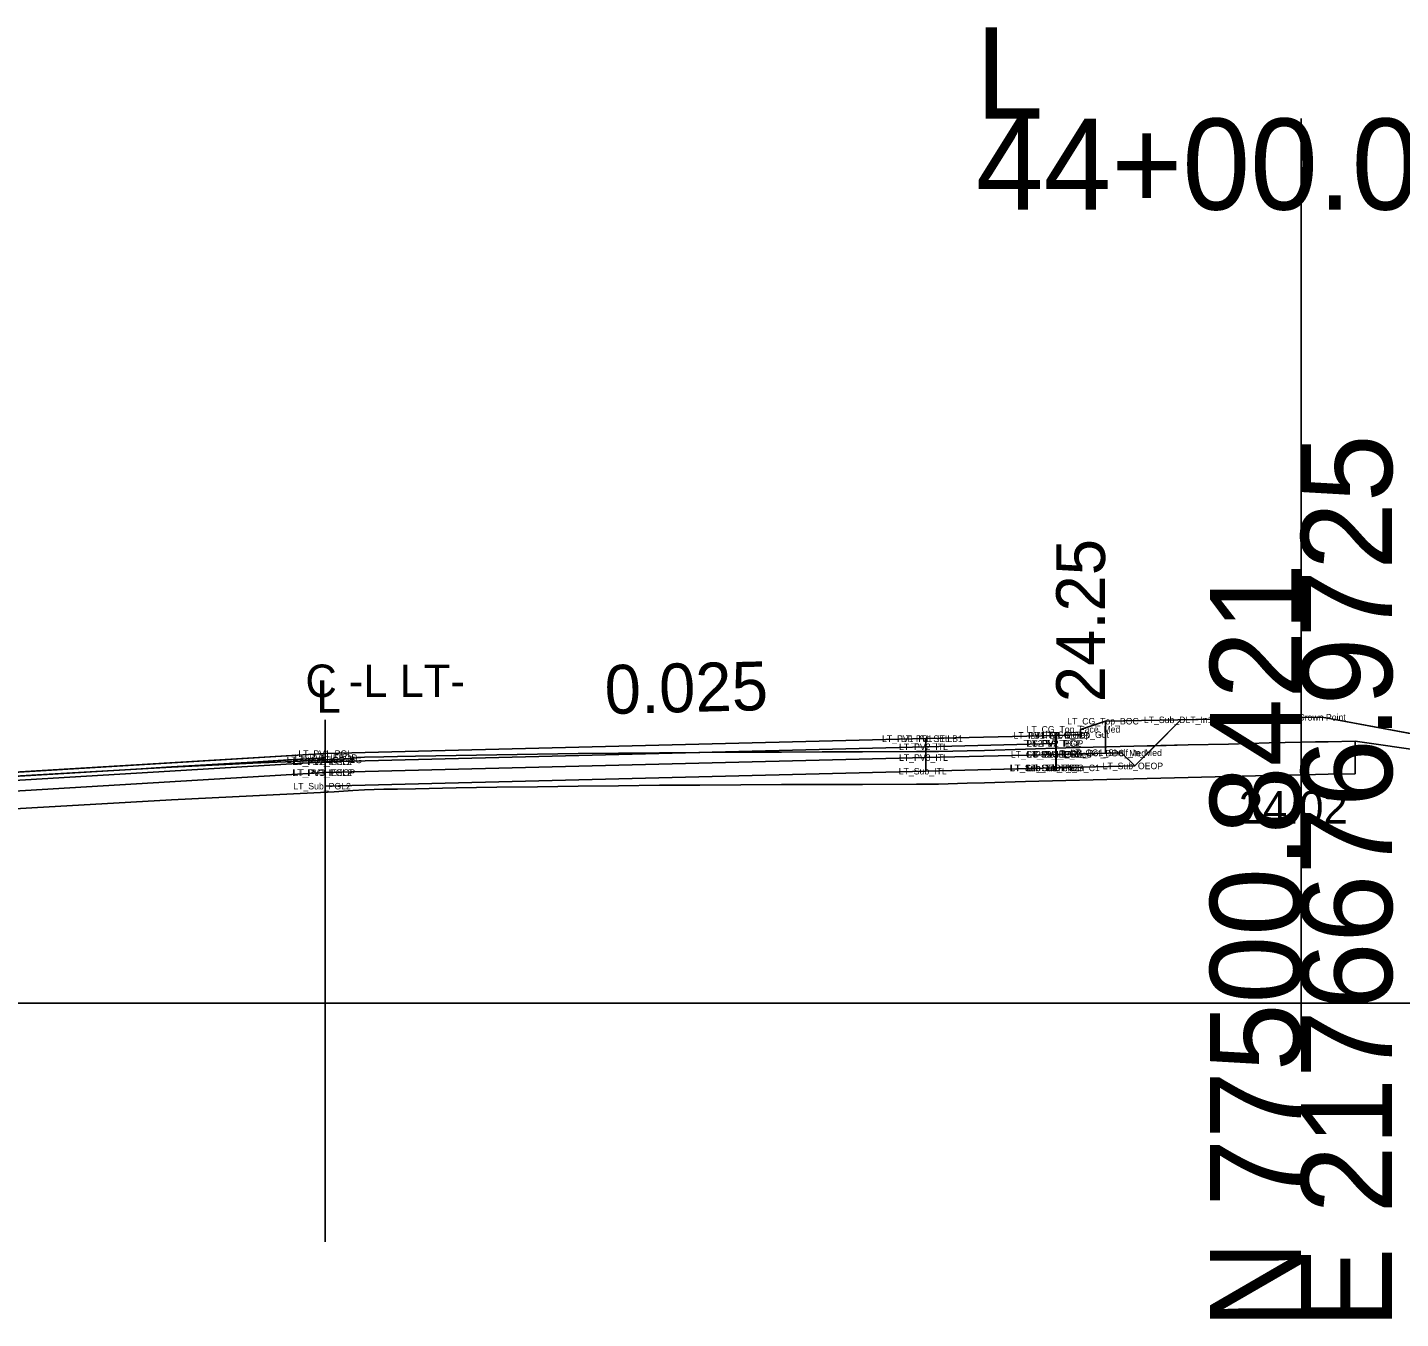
# Model space of a CAD drawing. Extents: x 2177029 to 2201446, y 59897 to 78390.
# Drawn here: x 2200203.58 to 2200245.79, y 64897.62 to 64937.3 of the extents above; entities that cross this region are included whole.
import ezdxf

# ---------------------------------------------------------------- set-up
doc = ezdxf.new("R2010")
doc.units = 0
for name, color, linetype in [('Exist CMT Pavement', 7, 'Continuous'), ('Exist Cross Section Cell', 7, 'Continuous'), ('Exist PHM Roadway Shape', 7, 'Continuous'), ('Exist XS Center Line Elevation Label', 7, 'Continuous'), ('Exist XS Ground Line', 7, 'Continuous'), ('Old_Level_11', 7, 'Continuous'), ('Old_Level_2', 7, 'Continuous'), ('Prop CMT Conc Surface', 7, 'Continuous'), ('Prop CMT Concrete Structures', 7, 'Continuous'), ('Prop CMT Guardrail Graphics', 7, 'Continuous'), ('Prop CMT Pvmt Course 1 CG', 7, 'Continuous'), ('Prop CMT Pvmt Course 2', 7, 'Continuous'), ('Prop CMT Pvmt Course 2 CG', 7, 'Continuous'), ('Prop CMT Pvmt Course 3', 7, 'Continuous'), ('Prop CMT Pvmt Course 4', 7, 'Continuous'), ('Prop CMT Pvmt Surface', 7, 'Continuous'), ('Prop CMT Pvmt Wedge Surface 1', 7, 'Continuous'), ('Prop CMT Slope Grass', 7, 'Continuous'), ('Prop CMT Subgrade Earthwork', 7, 'Continuous'), ('Prop CMT Top Wall Envelope', 7, 'Continuous'), ('Prop Hatching', 7, 'Continuous'), ('Prop Horizontal Alignment', 7, 'Continuous'), ('Prop Retaining Wall', 7, 'Continuous'), ('Prop Terminator CELL', 7, 'Continuous'), ('Prop XS Side Slope Text', 7, 'Continuous'), ('Scratch_Level_0', 7, 'Continuous'), ('Scratch_Level_9', 7, 'Continuous')]:
    doc.layers.add(name, color=color, linetype=linetype)

msp = doc.modelspace()

# ---------------------------------------------------------------- linework, layer by layer
at = {"layer": 'Exist CMT Pavement'}
msp.add_line((2200212.732, 64899.977), (2200212.732, 64916.023), dxfattribs=at)
at = {"layer": 'Exist Cross Section Cell'}
for p, q in [((2200242.732, 64907.31), (2200242.732, 64934.502)), ((2200042.732, 64907.31), (2200242.732, 64907.31)), ((2200242.732, 64907.31), (2200442.732, 64907.31))]:
    msp.add_line(p, q, dxfattribs=at)
at = {"layer": 'Exist XS Ground Line'}
msp.add_lwpolyline([(2200203.006, 64914.277), (2200204.255, 64914.347), (2200205.506, 64914.417), (2200206.756, 64914.49), (2200208.006, 64914.561), (2200209.258, 64914.622), (2200210.506, 64914.685), (2200211.758, 64914.744), (2200213.006, 64914.802), (2200213.582, 64914.846), (2200213.939, 64914.871), (2200214.536, 64914.887), (2200214.956, 64914.894), (2200215.506, 64914.904), (2200216.759, 64914.925), (2200218.007, 64914.947), (2200219.26, 64914.964), (2200220.506, 64914.981), (2200221.752, 64914.994), (2200223.006, 64915.008), (2200224.252, 64915.017), (2200225.506, 64915.025), (2200226.761, 64915.03), (2200228.007, 64915.033), (2200229.252, 64915.034), (2200230.911, 64915.046), (2200231.589, 64915.047), (2200232.467, 64915.072), (2200233.006, 64915.081), (2200234.261, 64915.12), (2200235.506, 64915.156), (2200236.762, 64915.189), (2200238.006, 64915.219), (2200239.262, 64915.249), (2200240.506, 64915.275), (2200241.749, 64915.309), (2200242.732, 64915.333), (2200243.173, 64915.343), (2200243.561, 64915.347), (2200244.4, 64915.365), (2200246.609, 64915.049)], dxfattribs=at)
at = {"layer": 'Old_Level_2'}
msp.add_line((2200242.732, 64905.938), (2200242.732, 64922.682), dxfattribs=at)
at = {"layer": 'Prop CMT Conc Surface'}
for points in [[(2200212.732, 64914.856), (2200177.17, 64912.722)], [(2200212.732, 64914.981), (2200212.732, 64914.731), (2200212.732, 64914.731), (2200212.732, 64914.856)]]:
    msp.add_lwpolyline(points, dxfattribs=at)
at = {"layer": 'Prop CMT Concrete Structures'}
for p, q in [((2200235.195, 64915.542), (2200235.204, 64915.542)), ((2200235.204, 64915.542), (2200235.205, 64915.543)), ((2200212.732, 64914.981), (2200231.197, 64915.442)), ((2200231.197, 64915.442), (2200231.196, 64915.442)), ((2200212.732, 64914.981), (2200176.732, 64912.821))]:
    msp.add_line(p, q, dxfattribs=at)
at = {"layer": 'Prop CMT Guardrail Graphics'}
for points in [[(2200212.732, 64914.981), (2200212.732, 64914.397)], [(2200212.732, 64914.397), (2200176.732, 64912.237)]]:
    msp.add_lwpolyline(points, dxfattribs=at)
at = {"layer": 'Prop CMT Pvmt Course 1 CG'}
for points in [[(2200235.195, 64914.959), (2200231.196, 64914.859)], [(2200231.196, 64914.859), (2200231.196, 64914.442)], [(2200235.195, 64914.542), (2200235.195, 64914.959)], [(2200231.196, 64914.442), (2200235.195, 64914.542)]]:
    msp.add_lwpolyline(points, dxfattribs=at)
at = {"layer": 'Prop CMT Pvmt Course 2'}
for points in [[(2200212.732, 64914.397), (2200231.196, 64914.859)], [(2200231.196, 64914.859), (2200231.196, 64914.442)], [(2200235.195, 64914.959), (2200235.205, 64914.959)], [(2200235.195, 64914.542), (2200235.195, 64914.959)], [(2200235.205, 64914.959), (2200235.205, 64914.543)], [(2200231.196, 64914.442), (2200212.732, 64913.981)], [(2200212.732, 64913.981), (2200212.732, 64914.397)], [(2200235.205, 64914.543), (2200235.195, 64914.542)]]:
    msp.add_lwpolyline(points, dxfattribs=at)
at = {"layer": 'Prop CMT Pvmt Course 2 CG'}
for points in [[(2200235.195, 64915.542), (2200235.205, 64915.543)], [(2200235.195, 64915.292), (2200235.195, 64915.542)], [(2200235.205, 64915.543), (2200235.205, 64915.293)], [(2200212.732, 64914.981), (2200231.196, 64915.442)], [(2200231.196, 64915.192), (2200212.732, 64914.731)], [(2200231.196, 64915.442), (2200231.196, 64915.192)], [(2200235.205, 64915.293), (2200235.195, 64915.292)], [(2200212.732, 64914.981), (2200176.732, 64912.821)], [(2200177.17, 64912.722), (2200212.732, 64914.856)], [(2200212.732, 64914.731), (2200212.732, 64914.981)], [(2200212.732, 64914.731), (2200212.732, 64914.981)], [(2200212.732, 64914.856), (2200212.732, 64914.731), (2200212.732, 64914.731)]]:
    msp.add_lwpolyline(points, dxfattribs=at)
at = {"layer": 'Prop CMT Pvmt Course 3'}
msp.add_line((2200212.732, 64914.789), (2200212.732, 64913.981), dxfattribs=at)
for points in [[(2200239.039, 64916.02), (2200237.621, 64914.603)], [(2200212.732, 64913.981), (2200231.196, 64914.442)], [(2200231.196, 64914.442), (2200235.195, 64914.542)], [(2200235.195, 64914.542), (2200235.205, 64914.543)], [(2200235.205, 64914.543), (2200237.621, 64914.603)], [(2200235.205, 64914.543), (2200235.205, 64914.543)]]:
    msp.add_lwpolyline(points, dxfattribs=at)
at = {"layer": 'Prop CMT Pvmt Course 4'}
msp.add_lwpolyline([(2200231.196, 64915.442), (2200235.195, 64915.542)], dxfattribs=at)
at = {"layer": 'Prop CMT Pvmt Surface'}
for points in [[(2200212.732, 64914.789), (2200211.758, 64914.744), (2200210.506, 64914.685), (2200209.258, 64914.622), (2200208.006, 64914.561), (2200206.756, 64914.49), (2200205.506, 64914.417), (2200204.255, 64914.347), (2200204.16, 64914.342)], [(2200204.255, 64914.348), (2200205.506, 64914.423), (2200206.756, 64914.498), (2200208.006, 64914.573), (2200209.258, 64914.648), (2200210.506, 64914.723), (2200211.758, 64914.798), (2200212.732, 64914.856)], [(2200212.732, 64914.856), (2200212.732, 64914.789)], [(2200204.16, 64914.342), (2200204.255, 64914.348)]]:
    msp.add_lwpolyline(points, dxfattribs=at)
at = {"layer": 'Prop CMT Pvmt Wedge Surface 1'}
for p, q in [((2200244.4, 64915.365), (2200244.4, 64914.365)), ((2200239.262, 64914.249), (2200240.506, 64914.275)), ((2200240.506, 64914.275), (2200241.749, 64914.309)), ((2200241.749, 64914.309), (2200242.732, 64914.333)), ((2200242.732, 64914.333), (2200243.173, 64914.343)), ((2200243.173, 64914.343), (2200243.561, 64914.347)), ((2200243.561, 64914.347), (2200244.4, 64914.365)), ((2200244.4, 64914.365), (2200244.4, 64914.365)), ((2200213.006, 64913.802), (2200213.582, 64913.846)), ((2200213.582, 64913.846), (2200213.939, 64913.871)), ((2200213.939, 64913.871), (2200214.536, 64913.887)), ((2200214.536, 64913.887), (2200214.956, 64913.894)), ((2200214.956, 64913.894), (2200215.506, 64913.904)), ((2200215.506, 64913.904), (2200216.759, 64913.925)), ((2200216.759, 64913.925), (2200218.007, 64913.947)), ((2200218.007, 64913.947), (2200219.26, 64913.964)), ((2200219.26, 64913.964), (2200220.506, 64913.981)), ((2200220.506, 64913.981), (2200221.752, 64913.994)), ((2200221.752, 64913.994), (2200223.006, 64914.008)), ((2200223.006, 64914.008), (2200224.252, 64914.017)), ((2200224.252, 64914.017), (2200225.506, 64914.025)), ((2200225.506, 64914.025), (2200226.761, 64914.03)), ((2200226.761, 64914.03), (2200228.007, 64914.033)), ((2200228.007, 64914.033), (2200229.252, 64914.034)), ((2200229.252, 64914.034), (2200230.911, 64914.046)), ((2200230.911, 64914.046), (2200231.589, 64914.047)), ((2200231.589, 64914.047), (2200232.467, 64914.072)), ((2200232.467, 64914.072), (2200233.006, 64914.081)), ((2200233.006, 64914.081), (2200234.261, 64914.12)), ((2200234.261, 64914.12), (2200235.506, 64914.156)), ((2200235.506, 64914.156), (2200236.762, 64914.189)), ((2200236.762, 64914.189), (2200238.006, 64914.219)), ((2200238.006, 64914.219), (2200239.262, 64914.249)), ((2200205.506, 64913.417), (2200206.756, 64913.49)), ((2200206.756, 64913.49), (2200208.006, 64913.561)), ((2200208.006, 64913.561), (2200209.258, 64913.622)), ((2200209.258, 64913.622), (2200210.506, 64913.685)), ((2200210.506, 64913.685), (2200211.758, 64913.744)), ((2200211.758, 64913.744), (2200213.006, 64913.802)), ((2200203.006, 64913.277), (2200204.255, 64913.347)), ((2200204.255, 64913.347), (2200205.506, 64913.417))]:
    msp.add_line(p, q, dxfattribs=at)
at = {"layer": 'Prop CMT Slope Grass'}
for points in [[(2200212.732, 64914.731), (2200231.196, 64915.192)], [(2200231.196, 64915.192), (2200231.196, 64914.859)], [(2200235.195, 64915.292), (2200235.205, 64915.293)], [(2200235.195, 64914.959), (2200235.195, 64915.292)], [(2200235.205, 64915.293), (2200235.205, 64914.959)], [(2200231.196, 64914.859), (2200212.732, 64914.397)], [(2200212.732, 64914.397), (2200212.732, 64914.731)], [(2200235.205, 64914.959), (2200235.195, 64914.959)]]:
    msp.add_lwpolyline(points, dxfattribs=at)
at = {"layer": 'Prop CMT Subgrade Earthwork'}
for points in [[(2200212.732, 64914.731), (2200176.732, 64912.571)], [(2200212.732, 64914.981), (2200212.732, 64914.731)]]:
    msp.add_lwpolyline(points, dxfattribs=at)
at = {"layer": 'Prop Hatching'}
for points in [[(2200236.716, 64915.978), (2200243.377, 64916.098)], [(2200250.039, 64914.876), (2200243.377, 64916.098)]]:
    msp.add_lwpolyline(points, dxfattribs=at)
at = {"layer": 'Prop Horizontal Alignment'}
for points in [[(2200235.205, 64914.959), (2200237.215, 64915.009), (2200237.621, 64914.603)], [(2200235.205, 64914.543), (2200235.205, 64914.959)], [(2200237.621, 64914.603), (2200235.205, 64914.543)]]:
    msp.add_lwpolyline(points, dxfattribs=at)
at = {"layer": 'Prop Retaining Wall'}
msp.add_lwpolyline([(2200235.205, 64915.543), (2200235.955, 64915.561), (2200235.957, 64915.728), (2200236.716, 64915.978)], dxfattribs=at)
at = {"layer": 'Prop Terminator CELL'}
for points in [[(2200235.205, 64915.543), (2200235.955, 64915.561), (2200235.957, 64915.728), (2200236.716, 64915.978)], [(2200236.716, 64915.978), (2200236.716, 64914.997)], [(2200235.205, 64914.959), (2200235.205, 64915.543)], [(2200236.716, 64914.997), (2200235.205, 64914.959)]]:
    msp.add_lwpolyline(points, dxfattribs=at)
at = {"layer": 'Prop XS Side Slope Text'}
for points in [[(2200241.749, 64915.309), (2200242.732, 64915.333), (2200242.732, 64916.087), (2200239.039, 64916.02), (2200238.243, 64915.225), (2200239.262, 64915.249), (2200240.506, 64915.275)], [(2200242.732, 64916.087), (2200243.377, 64916.098), (2200247.129, 64915.41), (2200247.638, 64914.901), (2200246.609, 64915.049), (2200244.4, 64915.365), (2200243.561, 64915.347), (2200243.173, 64915.343), (2200242.732, 64915.333)], [(2200212.732, 64914.789), (2200213.006, 64914.802), (2200213.582, 64914.846), (2200213.939, 64914.871), (2200214.536, 64914.887), (2200214.956, 64914.894), (2200215.506, 64914.904), (2200216.759, 64914.925), (2200218.007, 64914.947), (2200219.26, 64914.964), (2200220.506, 64914.981), (2200221.752, 64914.994), (2200223.006, 64915.008), (2200224.252, 64915.017), (2200225.506, 64915.025), (2200226.761, 64915.03), (2200228.007, 64915.033), (2200229.252, 64915.034), (2200230.911, 64915.046), (2200231.589, 64915.047), (2200232.467, 64915.072), (2200233.006, 64915.081), (2200234.261, 64915.12), (2200235.506, 64915.156), (2200236.762, 64915.189), (2200238.006, 64915.219), (2200238.243, 64915.225), (2200237.621, 64914.603), (2200235.205, 64914.543), (2200231.196, 64914.442), (2200212.732, 64913.981)]]:
    msp.add_lwpolyline(points, close=True, dxfattribs=at)
at = {"layer": 'Scratch_Level_0'}
for points in [[(2200231.196, 64915.192), (2200235.195, 64915.292)], [(2200231.196, 64914.859), (2200231.196, 64915.192)], [(2200235.195, 64915.292), (2200235.195, 64914.959)], [(2200235.195, 64914.959), (2200231.196, 64914.859)]]:
    msp.add_lwpolyline(points, dxfattribs=at)
at = {"layer": 'Scratch_Level_9'}
for points in [[(2200231.196, 64915.442), (2200235.195, 64915.542)], [(2200235.195, 64915.542), (2200235.195, 64915.292)], [(2200231.196, 64915.192), (2200231.196, 64915.442)], [(2200235.195, 64915.292), (2200231.196, 64915.192)]]:
    msp.add_lwpolyline(points, dxfattribs=at)

# ---------------------------------------------------------------- texts
at = {"layer": 'Exist CMT Pavement'}
for s, p in [('C -L LT-', (2200212.126, 64916.719)), ('L', (2200212.47, 64916.238))]:
    msp.add_text(s, height=1, dxfattribs=at).set_placement(p)
at = {"layer": 'Exist Cross Section Cell'}
for s, p in [('L', (2200232.732, 64934.502)), ('44+00.00 / 1', (2200232.732, 64931.702))]:
    msp.add_text(s, height=2.8, dxfattribs=at).set_placement(p)
for s, p in [('E 2176676.9725', (2200245.532, 64897.31)), ('N 77500.8421', (2200242.732, 64897.31))]:
    msp.add_text(s, height=2.8, rotation=90, dxfattribs=at).set_placement(p)
at = {"layer": 'Exist PHM Roadway Shape'}
for s, p in [('LT_CG_Top_BOC', (2200235.544, 64915.878)), ('LT_Sub_DLT_In1', (2200237.9, 64915.92)), ('MD_Crown Point', (2200242.084, 64915.998)), ('LT_PV1_ITL SE LB1', (2200229.852, 64915.342)), ('LT_PV1_ITL', (2200230.432, 64915.342)), ('LT_PV1_ITL SE LB', (2200233.892, 64915.442)), ('LT_CG_Top_Face_Med', (2200234.294, 64915.628)), ('PS1_LT_IEOP', (2200234.34, 64915.442)), ('LT_PV1_ITL1', (2200234.408, 64915.443)), ('LT_CG_Top_Gut', (2200234.779, 64915.461)), ('LT_PV2_ITL', (2200230.375, 64915.092)), ('PS2_LT_IEOP', (2200234.283, 64915.192)), ('LT_PV2_ITL2', (2200234.295, 64915.193)), ('LT_PV2_PGL', (2200234.316, 64915.192)), ('LT_CG1_Shelf_In_Med', (2200235.644, 64914.909)), ('LT_PV_IEEOP_EG', (2200211.551, 64914.689)), ('LT_PV2_IEEOP', (2200211.727, 64914.631)), ('LT_PV2_PGL2', (2200211.763, 64914.631)), ('LT_PV1_IEEOP', (2200211.784, 64914.756)), ('LT_PV1_PGL', (2200211.91, 64914.881)), ('LT_PV3_ITL', (2200230.375, 64914.759)), ('LT_CG_Bot_IE_Med', (2200233.811, 64914.859)), ('LT_PV3_ITL2', (2200234.295, 64914.859)), ('LT_PV3_PGL', (2200234.316, 64914.859)), ('PS3_IEOP', (2200234.553, 64914.859)), ('LT_CG_Bot_BOC_Med', (2200235.158, 64914.897)), ('LT_Sub_OEOP', (2200236.632, 64914.503)), ('LT_PV3_IEEOP', (2200211.727, 64914.297)), ('LT_PV3_PGL2', (2200211.763, 64914.297)), ('LT_Sub_ITL', (2200230.366, 64914.342)), ('LT_Sub_Trench_In', (2200233.778, 64914.442)), ('LT_Sub_IEOT_CG_C1', (2200233.797, 64914.443)), ('LT_Sub_ITL2', (2200234.285, 64914.443)), ('LT_Sub_PGL', (2200234.307, 64914.442)), ('LT_Sub_PGL2', (2200211.754, 64913.881))]:
    msp.add_text(s, height=0.2, dxfattribs=at).set_placement(p)
at = {"layer": 'Exist XS Center Line Elevation Label'}
msp.add_text('24.02', height=1, dxfattribs=at).set_placement((2200240.819, 64912.833))
at = {"layer": 'Old_Level_11'}
msp.add_text('0.025', height=1.5, rotation=1.4325, dxfattribs=at).set_placement((2200221.343, 64916.197))
at = {"layer": 'Prop CMT Top Wall Envelope'}
msp.add_text('24.25', height=1.5, rotation=90, dxfattribs=at).set_placement((2200236.705, 64916.561))

doc.saveas('drawing.dxf')
